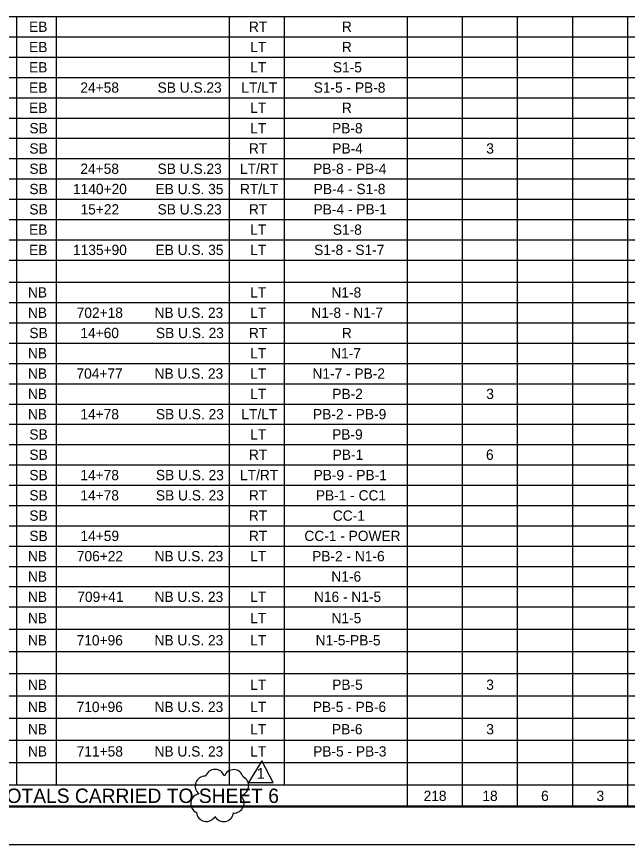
# Model space of a CAD drawing. Extents: x 0 to 34, y 0 to 22.
# Drawn here: x 4.68 to 12.63, y 0 to 10.78 of the extents above; entities that cross this region are included whole.
import ezdxf

# ---------------------------------------------------------------- set-up
doc = ezdxf.new("R2010")
doc.units = 0
for name, color, linetype in [('Default', 7, 'Continuous'), ('SH_Border', 7, 'Continuous'), ('SH_Cut_Line', 7, 'Continuous')]:
    doc.layers.add(name, color=color, linetype=linetype)

msp = doc.modelspace()

# ---------------------------------------------------------------- linework, layer by layer
at = {"layer": 'Default'}
for p, q in [((2.519, 10.78), (4.683, 10.78)), ((4.683, 10.78), (11.918, 10.78)), ((4.683, 10.78), (4.683, 10.252)), ((5.199, 10.78), (5.199, 10.252)), ((7.451, 10.78), (7.451, 10.252)), ((8.168, 10.78), (8.168, 10.252)), ((9.766, 10.78), (9.766, 10.252)), ((10.483, 10.78), (10.483, 10.252)), ((11.201, 10.78), (11.201, 10.252)), ((11.918, 10.78), (12.635, 10.78)), ((11.918, 10.78), (11.918, 10.252)), ((12.635, 10.78), (13.352, 10.78)), ((12.635, 10.78), (12.635, 10.252)), ((2.519, 10.516), (4.683, 10.516)), ((4.683, 10.516), (11.918, 10.516)), ((11.918, 10.516), (12.635, 10.516)), ((12.635, 10.516), (13.352, 10.516)), ((2.519, 10.252), (4.683, 10.252)), ((4.683, 10.252), (11.918, 10.252)), ((4.683, 10.252), (4.683, 9.459)), ((5.199, 10.252), (5.199, 9.459)), ((7.451, 10.252), (7.451, 9.459)), ((8.168, 10.252), (8.168, 9.459)), ((9.766, 10.252), (9.766, 9.459)), ((10.483, 10.252), (10.483, 9.459)), ((11.201, 10.252), (11.201, 9.459)), ((11.918, 10.252), (12.635, 10.252)), ((11.918, 10.252), (11.918, 9.459)), ((12.635, 10.252), (13.352, 10.252)), ((12.635, 10.252), (12.635, 9.459)), ((2.519, 9.988), (4.683, 9.988)), ((4.683, 9.988), (11.918, 9.988)), ((11.918, 9.988), (12.635, 9.988)), ((12.635, 9.988), (13.352, 9.988)), ((2.519, 9.723), (4.683, 9.723)), ((4.683, 9.723), (11.918, 9.723)), ((11.918, 9.723), (12.635, 9.723)), ((12.635, 9.723), (13.352, 9.723)), ((2.519, 9.459), (4.683, 9.459)), ((4.683, 9.459), (11.918, 9.459)), ((4.683, 9.459), (4.683, 8.931)), ((5.199, 9.459), (5.199, 8.931)), ((7.451, 9.459), (7.451, 8.931)), ((8.168, 9.459), (8.168, 8.931)), ((9.766, 9.459), (9.766, 8.931)), ((10.483, 9.459), (10.483, 8.931)), ((11.201, 9.459), (11.201, 8.931)), ((11.918, 9.459), (12.635, 9.459)), ((11.918, 9.459), (11.918, 8.931)), ((12.635, 9.459), (13.352, 9.459)), ((12.635, 9.459), (12.635, 8.931)), ((2.519, 9.195), (4.683, 9.195)), ((4.683, 9.195), (11.918, 9.195)), ((11.918, 9.195), (12.635, 9.195)), ((12.635, 9.195), (13.352, 9.195)), ((2.519, 8.931), (4.683, 8.931)), ((4.683, 8.931), (11.918, 8.931)), ((4.683, 8.931), (4.683, 8.138)), ((5.199, 8.931), (5.199, 8.138)), ((7.451, 8.931), (7.451, 8.138)), ((8.168, 8.931), (8.168, 8.138)), ((9.766, 8.931), (9.766, 8.138)), ((10.483, 8.931), (10.483, 8.138)), ((11.201, 8.931), (11.201, 8.138)), ((11.918, 8.931), (12.635, 8.931)), ((11.918, 8.931), (11.918, 8.138)), ((12.635, 8.931), (13.352, 8.931)), ((12.635, 8.931), (12.635, 8.138)), ((2.519, 8.667), (4.683, 8.667)), ((4.683, 8.667), (11.918, 8.667)), ((11.918, 8.667), (12.635, 8.667)), ((12.635, 8.667), (13.352, 8.667)), ((2.519, 8.402), (4.683, 8.402)), ((4.683, 8.402), (11.918, 8.402)), ((11.918, 8.402), (12.635, 8.402)), ((12.635, 8.402), (13.352, 8.402)), ((2.519, 8.138), (4.683, 8.138)), ((4.683, 8.138), (11.918, 8.138)), ((4.683, 8.138), (4.683, 7.61)), ((5.199, 8.138), (5.199, 7.61)), ((7.451, 8.138), (7.451, 7.61)), ((8.168, 8.138), (8.168, 7.61)), ((9.766, 8.138), (9.766, 7.61)), ((10.483, 8.138), (10.483, 7.61)), ((11.201, 8.138), (11.201, 7.61)), ((11.918, 8.138), (12.635, 8.138)), ((11.918, 8.138), (11.918, 7.61)), ((12.635, 8.138), (13.352, 8.138)), ((12.635, 8.138), (12.635, 7.61)), ((2.519, 7.874), (4.683, 7.874)), ((4.683, 7.874), (11.918, 7.874)), ((11.918, 7.874), (12.635, 7.874)), ((12.635, 7.874), (13.352, 7.874)), ((2.519, 7.61), (4.683, 7.61)), ((4.683, 7.61), (11.918, 7.61)), ((4.683, 7.61), (4.683, 7.32)), ((5.199, 7.61), (5.199, 7.32)), ((7.451, 7.61), (7.451, 7.32)), ((8.168, 7.61), (8.168, 7.32)), ((9.766, 7.61), (9.766, 7.32)), ((10.483, 7.61), (10.483, 7.32)), ((11.201, 7.61), (11.201, 7.32)), ((11.918, 7.61), (12.635, 7.61)), ((11.918, 7.61), (11.918, 7.32)), ((12.635, 7.61), (13.352, 7.61)), ((12.635, 7.61), (12.635, 7.32)), ((2.519, 7.32), (4.683, 7.32)), ((4.683, 7.32), (11.918, 7.32)), ((4.683, 7.32), (4.683, 1.935)), ((5.199, 7.32), (5.199, 1.935)), ((7.451, 7.32), (7.451, 1.935)), ((8.168, 7.32), (8.168, 1.935)), ((9.766, 7.32), (9.766, 1.935)), ((10.483, 7.32), (10.483, 1.935)), ((11.201, 7.32), (11.201, 1.935)), ((11.918, 7.32), (12.635, 7.32)), ((11.918, 7.32), (11.918, 1.935)), ((12.635, 7.32), (13.352, 7.32)), ((12.635, 7.32), (12.635, 1.935)), ((2.519, 7.056), (4.683, 7.056)), ((4.683, 7.056), (11.918, 7.056)), ((11.918, 7.056), (12.635, 7.056)), ((12.635, 7.056), (13.352, 7.056)), ((2.519, 6.792), (4.683, 6.792)), ((4.683, 6.792), (11.918, 6.792)), ((11.918, 6.792), (12.635, 6.792)), ((12.635, 6.792), (13.352, 6.792)), ((2.519, 6.528), (4.683, 6.528)), ((4.683, 6.528), (11.918, 6.528)), ((11.918, 6.528), (12.635, 6.528)), ((12.635, 6.528), (13.352, 6.528)), ((2.519, 6.263), (4.683, 6.263)), ((4.683, 6.263), (11.918, 6.263)), ((11.918, 6.263), (12.635, 6.263)), ((12.635, 6.263), (13.352, 6.263)), ((2.519, 5.999), (4.683, 5.999)), ((4.683, 5.999), (11.918, 5.999)), ((11.918, 5.999), (12.635, 5.999)), ((12.635, 5.999), (13.352, 5.999)), ((2.519, 5.735), (4.683, 5.735)), ((4.683, 5.735), (11.918, 5.735)), ((11.918, 5.735), (12.635, 5.735)), ((12.635, 5.735), (13.352, 5.735)), ((2.519, 5.471), (4.683, 5.471)), ((4.683, 5.471), (11.918, 5.471)), ((11.918, 5.471), (12.635, 5.471)), ((12.635, 5.471), (13.352, 5.471)), ((2.519, 5.207), (4.683, 5.207)), ((4.683, 5.207), (11.918, 5.207)), ((11.918, 5.207), (12.635, 5.207)), ((12.635, 5.207), (13.352, 5.207)), ((2.519, 4.942), (4.683, 4.942)), ((4.683, 4.942), (11.918, 4.942)), ((11.918, 4.942), (12.635, 4.942)), ((12.635, 4.942), (13.352, 4.942)), ((2.519, 4.678), (4.683, 4.678)), ((4.683, 4.678), (11.918, 4.678)), ((11.918, 4.678), (12.635, 4.678)), ((12.635, 4.678), (13.352, 4.678)), ((2.519, 4.414), (4.683, 4.414)), ((4.683, 4.414), (11.918, 4.414)), ((11.918, 4.414), (12.635, 4.414)), ((12.635, 4.414), (13.352, 4.414)), ((2.519, 4.15), (4.683, 4.15)), ((4.683, 4.15), (11.918, 4.15)), ((11.918, 4.15), (12.635, 4.15)), ((12.635, 4.15), (13.352, 4.15)), ((2.519, 3.886), (4.683, 3.886)), ((4.683, 3.886), (11.918, 3.886)), ((11.918, 3.886), (12.635, 3.886)), ((12.635, 3.886), (13.352, 3.886)), ((2.519, 3.621), (4.683, 3.621)), ((4.683, 3.621), (11.918, 3.621)), ((11.918, 3.621), (12.635, 3.621)), ((12.635, 3.621), (13.352, 3.621)), ((2.519, 3.357), (4.683, 3.357)), ((4.683, 3.357), (11.918, 3.357)), ((11.918, 3.357), (12.635, 3.357)), ((12.635, 3.357), (13.352, 3.357)), ((2.519, 3.093), (4.683, 3.093)), ((4.683, 3.093), (11.918, 3.093)), ((11.918, 3.093), (12.635, 3.093)), ((12.635, 3.093), (13.352, 3.093)), ((2.519, 2.803), (4.683, 2.803)), ((4.683, 2.803), (11.918, 2.803)), ((11.918, 2.803), (12.635, 2.803)), ((12.635, 2.803), (13.352, 2.803)), ((2.519, 2.514), (4.683, 2.514)), ((4.683, 2.514), (11.918, 2.514)), ((11.918, 2.514), (12.635, 2.514)), ((12.635, 2.514), (13.352, 2.514)), ((2.519, 2.225), (4.683, 2.225)), ((4.683, 2.225), (11.918, 2.225)), ((11.918, 2.225), (12.635, 2.225)), ((12.635, 2.225), (13.352, 2.225)), ((2.519, 1.935), (4.683, 1.935)), ((4.683, 1.935), (11.918, 1.935)), ((4.683, 1.935), (4.683, 1.646)), ((5.199, 1.935), (5.199, 1.646)), ((7.451, 1.935), (7.451, 1.646)), ((8.168, 1.935), (8.168, 1.646)), ((9.766, 1.935), (9.766, 1.646)), ((10.483, 1.935), (10.483, 1.646)), ((11.201, 1.935), (11.201, 1.646)), ((11.918, 1.935), (12.635, 1.935)), ((11.918, 1.935), (11.918, 1.646)), ((12.635, 1.935), (13.352, 1.935)), ((12.635, 1.935), (12.635, 1.646)), ((2.519, 1.646), (4.683, 1.646)), ((4.683, 1.646), (11.918, 1.646)), ((4.683, 1.646), (4.683, 0.778)), ((5.199, 1.646), (5.199, 0.778)), ((7.451, 1.646), (7.451, 0.778)), ((8.168, 1.646), (8.168, 0.778)), ((9.766, 1.646), (9.766, 0.488)), ((10.483, 1.646), (10.483, 0.488)), ((11.201, 1.646), (11.201, 0.488)), ((11.918, 1.646), (12.635, 1.646)), ((11.918, 1.646), (11.918, 0.488)), ((12.635, 1.646), (13.352, 1.646)), ((12.635, 1.646), (12.635, 0.488)), ((2.519, 1.357), (4.683, 1.357)), ((4.683, 1.357), (11.918, 1.357)), ((11.918, 1.357), (12.635, 1.357)), ((12.635, 1.357), (13.352, 1.357)), ((2.519, 1.067), (4.683, 1.067)), ((4.683, 1.067), (11.918, 1.067)), ((11.918, 1.067), (12.635, 1.067)), ((12.635, 1.067), (13.352, 1.067)), ((2.519, 0.778), (4.683, 0.778)), ((4.683, 0.778), (11.918, 0.778)), ((11.918, 0.778), (12.635, 0.778)), ((12.635, 0.778), (13.352, 0.778)), ((2.519, 0.488), (4.683, 0.488)), ((4.683, 0.488), (11.918, 0.488)), ((11.918, 0.488), (12.635, 0.488)), ((12.635, 0.488), (13.352, 0.488))]:
    msp.add_line(p, q, dxfattribs=at)
msp.add_lwpolyline([(7.875, 1.087), (7.704, 0.808), (8.024, 0.806)], close=True, dxfattribs=at)
for centre, radius, start, end in [((7.266, 0.85), 0.128, 17.5, 162.5), ((7.509, 0.846), 0.128, 15.2753, 160.2753), ((7.137, 0.761), 0.128, 87.1451, 232.1451), ((7.577, 0.764), 0.128, 279.3267, 64.3267), ((7.08, 0.533), 0.129, 99.7825, 244.7825), ((7.516, 0.538), 0.129, 265.3078, 50.3078), ((7.153, 0.428), 0.129, 185.4197, 330.4197), ((7.378, 0.425), 0.128, 208.0814, 353.0814)]:
    msp.add_arc(centre, radius, start, end, dxfattribs=at)
at = {"layer": 'SH_Border'}
msp.add_lwpolyline([(1.5, 21.5), (33.5, 21.5), (33.5, 0.5), (1.5, 0.5)], close=True, dxfattribs=at)
at = {"layer": 'SH_Cut_Line'}
msp.add_lwpolyline([(0, 0), (34, 0), (34, 22), (0, 22)], close=True, dxfattribs=at)

# ---------------------------------------------------------------- texts
at = {"layer": 'Default'}
for s, height, p in [('EB', 0.1337, (4.846, 10.581)), ('RT', 0.1337, (7.708, 10.581)), ('R', 0.134, (8.918, 10.581)), ('EB', 0.1337, (4.846, 10.317)), ('LT', 0.1337, (7.725, 10.317)), ('R', 0.134, (8.918, 10.317)), ('EB', 0.1337, (4.846, 10.053)), ('LT', 0.1337, (7.725, 10.053)), ('S1-5', 0.1337, (8.801, 10.053)), ('EB', 0.1337, (4.846, 9.789)), ('24+58', 0.1337, (5.514, 9.789)), ('SB U.S.23', 0.1337, (6.519, 9.789)), ('LT/LT', 0.1337, (7.609, 9.789)), ('S1-5 - PB-8', 0.13368, (8.551, 9.789)), ('EB', 0.1337, (4.846, 9.525)), ('LT', 0.1337, (7.725, 9.525)), ('R', 0.134, (8.918, 9.525)), ('SB', 0.1337, (4.85, 9.26)), ('LT', 0.1337, (7.725, 9.26)), ('PB-8', 0.1337, (8.79, 9.26)), ('SB', 0.1337, (4.85, 8.996)), ('RT', 0.1337, (7.708, 8.996)), ('PB-4', 0.1337, (8.793, 8.996)), ('3', 0.134, (10.797, 8.996)), ('SB', 0.1337, (4.85, 8.732)), ('24+58', 0.1337, (5.514, 8.732)), ('SB U.S.23', 0.1337, (6.519, 8.732)), ('LT/RT', 0.1337, (7.592, 8.732)), ('PB-8 - PB-4', 0.13368, (8.544, 8.732)), ('SB', 0.1337, (4.85, 8.468)), ('1140+20', 0.1337, (5.418, 8.468)), ('EB U.S. 35', 0.1337, (6.492, 8.468)), ('RT/LT', 0.1337, (7.592, 8.468)), ('PB-4 - S1-8', 0.13368, (8.551, 8.468)), ('SB', 0.1337, (4.85, 8.203)), ('15+22', 0.1337, (5.516, 8.203)), ('SB U.S.23', 0.1337, (6.519, 8.203)), ('RT', 0.1337, (7.708, 8.203)), ('PB-4 - PB-1', 0.13368, (8.549, 8.203)), ('EB', 0.1337, (4.846, 7.939)), ('LT', 0.1337, (7.725, 7.939)), ('S1-8', 0.1337, (8.8, 7.939)), ('EB', 0.1337, (4.846, 7.675)), ('1135+90', 0.1337, (5.418, 7.675)), ('EB U.S. 35', 0.1337, (6.492, 7.675)), ('LT', 0.1337, (7.725, 7.675)), ('S1-8 - S1-7', 0.13368, (8.557, 7.675)), ('NB', 0.1337, (4.831, 7.121)), ('LT', 0.1337, (7.725, 7.121)), ('N1-8', 0.1337, (8.782, 7.121)), ('NB', 0.1337, (4.831, 6.857)), ('702+18', 0.1337, (5.466, 6.857)), ('NB U.S. 23', 0.1337, (6.479, 6.857)), ('LT', 0.1337, (7.725, 6.857)), ('N1-8 - N1-7', 0.13368, (8.52, 6.857)), ('SB', 0.1337, (4.85, 6.593)), ('14+60', 0.1337, (5.514, 6.593)), ('SB U.S. 23', 0.1337, (6.497, 6.593)), ('RT', 0.1337, (7.708, 6.593)), ('R', 0.134, (8.918, 6.593)), ('NB', 0.1337, (4.831, 6.329)), ('LT', 0.1337, (7.725, 6.329)), ('N1-7', 0.1337, (8.778, 6.329)), ('NB', 0.1337, (4.831, 6.065)), ('704+77', 0.1337, (5.463, 6.065)), ('NB U.S. 23', 0.1337, (6.479, 6.065)), ('LT', 0.1337, (7.725, 6.065)), ('N1-7 - PB-2', 0.13368, (8.535, 6.065)), ('NB', 0.1337, (4.831, 5.8)), ('LT', 0.1337, (7.725, 5.8)), ('PB-2', 0.1337, (8.793, 5.8)), ('3', 0.134, (10.797, 5.8)), ('NB', 0.1337, (4.831, 5.536)), ('14+78', 0.1337, (5.514, 5.536)), ('SB U.S. 23', 0.1337, (6.497, 5.536)), ('LT/LT', 0.1337, (7.609, 5.536)), ('PB-2 - PB-9', 0.13368, (8.542, 5.536)), ('SB', 0.1337, (4.85, 5.272)), ('LT', 0.1337, (7.725, 5.272)), ('PB-9', 0.1337, (8.791, 5.272)), ('SB', 0.1337, (4.85, 5.008)), ('RT', 0.1337, (7.708, 5.008)), ('PB-1', 0.1337, (8.798, 5.008)), ('6', 0.134, (10.794, 5.008)), ('SB', 0.1337, (4.85, 4.743)), ('14+78', 0.1337, (5.514, 4.743)), ('SB U.S. 23', 0.1337, (6.497, 4.743)), ('LT/RT', 0.1337, (7.592, 4.743)), ('PB-9 - PB-1', 0.13368, (8.549, 4.743)), ('SB', 0.1337, (4.85, 4.479)), ('14+78', 0.1337, (5.514, 4.479)), ('SB U.S. 23', 0.1337, (6.497, 4.479)), ('RT', 0.1337, (7.708, 4.479)), ('PB-1 - CC1', 0.1337, (8.579, 4.479)), ('SB', 0.1337, (4.85, 4.215)), ('RT', 0.1337, (7.708, 4.215)), ('CC-1', 0.1337, (8.8, 4.215)), ('SB', 0.1337, (4.85, 3.951)), ('14+59', 0.1337, (5.515, 3.951)), ('RT', 0.1337, (7.708, 3.951)), ('CC-1 - POWER', 0.13368, (8.43, 3.951)), ('NB', 0.1337, (4.831, 3.687)), ('706+22', 0.1337, (5.468, 3.687)), ('NB U.S. 23', 0.1337, (6.479, 3.687)), ('LT', 0.1337, (7.725, 3.687)), ('PB-2 - N1-6', 0.13368, (8.531, 3.687)), ('N1-6', 0.1337, (8.781, 3.422)), ('NB', 0.1337, (4.831, 3.422)), ('NB', 0.1337, (4.831, 3.158)), ('709+41', 0.1337, (5.474, 3.158)), ('NB U.S. 23', 0.1337, (6.479, 3.158)), ('LT', 0.1337, (7.725, 3.158)), ('N16 - N1-5', 0.1337, (8.554, 3.158)), ('NB', 0.1337, (4.831, 2.881)), ('LT', 0.1337, (7.725, 2.881)), ('N1-5', 0.1337, (8.783, 2.881)), ('NB', 0.1337, (4.831, 2.592)), ('710+96', 0.1337, (5.465, 2.592)), ('NB U.S. 23', 0.1337, (6.479, 2.592)), ('LT', 0.1337, (7.725, 2.592)), ('N1-5-PB-5', 0.1337, (8.577, 2.592)), ('NB', 0.1337, (4.831, 2.013)), ('LT', 0.1337, (7.725, 2.013)), ('PB-5', 0.1337, (8.792, 2.013)), ('3', 0.134, (10.797, 2.013)), ('NB', 0.1337, (4.831, 1.724)), ('710+96', 0.1337, (5.465, 1.724)), ('NB U.S. 23', 0.1337, (6.479, 1.724)), ('LT', 0.1337, (7.725, 1.724)), ('PB-5 - PB-6', 0.13368, (8.54, 1.724)), ('NB', 0.1337, (4.831, 1.434)), ('LT', 0.1337, (7.725, 1.434)), ('PB-6', 0.1337, (8.789, 1.434)), ('3', 0.134, (10.797, 1.434)), ('NB', 0.1337, (4.831, 1.145)), ('711+58', 0.1337, (5.466, 1.145)), ('NB U.S. 23', 0.1337, (6.479, 1.145)), ('LT', 0.1337, (7.725, 1.145)), ('PB-5 - PB-3', 0.13368, (8.544, 1.145)), ('1', 0.14, (7.808, 0.855)), ('SUBTOTALS CARRIED TO SHEET 6', 0.18715, (3.885, 0.54)), ('218', 0.1337, (9.982, 0.566)), ('18', 0.1337, (10.747, 0.566)), ('6', 0.134, (11.511, 0.566)), ('3', 0.134, (12.232, 0.566))]:
    msp.add_text(s, height=height, dxfattribs=at).set_placement(p)

doc.saveas('drawing.dxf')
